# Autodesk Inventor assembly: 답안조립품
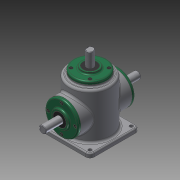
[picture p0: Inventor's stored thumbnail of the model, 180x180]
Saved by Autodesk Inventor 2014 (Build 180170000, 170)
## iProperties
Created: 2015-10
Part Number: 답안조립품
Document SubType Name: Assembly
Designer: 시험용
Author: 시험용
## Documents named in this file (14)
- C:\Users\시험용\Desktop\451007V1013\답안조립품.iam
- C:\Users\시험용\Desktop\451007V1013\M4.ipt
- C:\Users\시험용\Desktop\451007V1013\메인 베벨기어.ipt
- C:\Users\시험용\Desktop\451007V1013\메인 축.ipt
- 메인 축.ipt
- C:\Users\시험용\Desktop\451007V1013\베어링 6203.ipt
- C:\Users\시험용\Desktop\451007V1013\본체.ipt
- C:\Users\시험용\Desktop\451007V1013\서브 베벨기어.ipt
- C:\Users\시험용\Desktop\451007V1013\서브 축.ipt
- 서브 축.ipt
- C:\Users\시험용\Desktop\451007V1013\오일실.ipt
- C:\Users\시험용\Desktop\451007V1013\커버.ipt
- C:\Users\시험용\Desktop\451007V1013\키 4x4.ipt
- C:\Users\시험용\Desktop\451007V1013\키 5x5.ipt
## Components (12 placed, 1 different names)
1. M4:1
2. M4:2
3. M4:3
4. M4:4
5. M4:5
6. M4:6
7. M4:7
8. M4:8
9. M4:9
10. M4:10
11. M4:11
12. M4:12
